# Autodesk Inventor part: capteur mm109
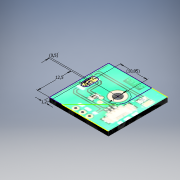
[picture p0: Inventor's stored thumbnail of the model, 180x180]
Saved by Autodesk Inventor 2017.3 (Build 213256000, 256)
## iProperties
Part Number: capteur mm109
Material: Générique
Document SubType Name: Modeling
Designer: ficho
Density: 1 g/cm^3
Appearance: Par défaut
Author: ficho
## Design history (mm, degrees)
sketch "Esquisse1"
  geometry: L1 (0, 0)-(22, 0); L2 (22, 0)-(22, 22); L3 (22, 22)-(0, 22); L4 (0, 22)-(0, 0); C1 r 1.5 at (9.5, 10); C2 r 0.5 at (20.359, 16); C3 r 0.5 at (20.359, 11); C4 r 0.5 at (20.359, 6)
  constraints: 8 end point, 4 centre point, 2 parallel, 1 horizontal, 1 perpendicular
  dimensions: "d0" = 22 distance of L3.end L2.end; "d1" = 22 distance of L2.end L1.end; "d2" = 3 diameter of C1; "d3" = 12.5 distance from line of L2 C1.centre; "d4" = 12 distance from line of C1.centre L3; "d5" = 6 distance from line of C2.centre L3 (computed from d6); "d6" = 5 distance of C3.centre C2.centre; "d7" = 5 distance of C4.centre C3.centre (= d6); "d8" = 1 diameter of C2; "d9" = 1 diameter of C3 (= d8); "d10" = 1 diameter of C4
extrude "Extrusion1" new body sketch "Esquisse1" distance "d11" = 1.6; taper "d12" = 0 deg
node "Plan de construction1"
sketch "Esquisse2"
  geometry: L1 (-75, 72.5)-(284.333, 72.5); L2 (284.333, 72.5)-(284.333, -43); L3 (284.333, -43)-(-75, -43); L4 (-75, -43)-(-75, 72.5); 1 further point; 1 other entity
  constraints: 2 other
  dimensions: "d17" = 115.5 distance between parallel lines of L3 L1; "d21" = 43 distance from line of L3 point (0, 0); "d22" = 75 distance from line of L4 point (0, 0)
feature "Décalcomanie1" sketch "Esquisse2"
sketch "Esquisse3"
  geometry: L1 (0, 0)-(-22, 0) reference; L2 (0, 22)-(0, 0) reference; L3 (-22, 22)-(0, 22) reference; L4 (-22, 0)-(-22, 22) reference; C1 r 1.5 at (-9.5, 10) reference; C2 r 0.5 at (-20.359, 6) reference; C3 r 0.5 at (-20.359, 11) reference; C4 r 0.5 at (-20.359, 16) reference; 1 further point
extrude "Extrusion2" join sketch "Esquisse3" stored distance "d25" = 1.6; taper "d26" = 0 deg
sketch "Esquisse4"
  geometry: L1 (0, 0)-(22, 0) reference; L2 (0, 22)-(0, 0) reference; C1 r 1.5 at (12.5, 13); C2 r 0.375 at (8.394, 1.4); C3 r 0.375 at (10.974, 1.4); C4 r 0.375 at (13.554, 1.4)
  constraints: 4 centre point
  dimensions: "d27" = 3 diameter of C1; "d28" = 0.75 diameter of C2; "d29" = 0.75 diameter of C3 (= d28); "d30" = 0.75 diameter of C4 (= d29); "d31" = 2.58 distance of C3.centre C2.centre; "d32" = 2.58 distance of C3.centre C4.centre (= d31); "d33" = 1.4 distance from line of C2.centre L1; "d34" = 1.4 distance from line of L1 C3.centre (= d33); "d35" = 1.4 distance from line of L1 C4.centre (= d33); "d36" = 12.5 distance from line of L2 C1.centre; "d37" = 13 distance from line of L1 C1.centre
extrude "Extrusion3" cut sketch "Esquisse4" stored distance "d38" = 1.6; taper "d39" = 0 deg
sketch "Esquisse5"
  geometry: L1 (2.45, 14)-(2.45, 11); L2 (1.2, 14)-(1.2, 11); L3 (3.7, 11)-(3.7, 14); L4 (0, 22)-(0, 0) reference; L5 (0, 22)-(0, 0); L6 (14.993, 10.543)-(4.604, 0); L7 (0, 0)-(22, 0) reference; L8 (4.604, 0)-(0, 0); L9 (16, 13)-(16, 22); L10 (22, 22)-(0, 22) reference; L11 (16, 22)-(0, 22); A1 r 1.25 centre (2.45, 14) between (3.7, 14) and (1.2, 14); A2 r 1.25 centre (2.45, 11) between (1.2, 11) and (3.7, 11); A3 r 3.5 centre (12.5, 13) between (14.993, 10.543) and (16, 13); 2 further points
  constraints: 18 end point, 6 point on circle, 6 tangent, 3 centre point, 3 collinear, 2 vertical, 1 coincident, 1 midpoint, 1 parallel, 1 point on line
  dimensions: "d43" = 3 distance of L1.start L1.end; "d44" = 2.5 diameter of A2; "d45" = 1.2 distance between parallel lines of L2 L4; "d46" = 12.5 vertical distance of L4.end point (2.45, 12.5); "d47" = 7 diameter of A3; "d48" = 0.5 vertical distance of point (2.45, 12.5) point (12.5, 13) (derived); "d49" = 10.05 horizontal distance of point (12.5, 13) point (2.45, 12.5) (derived)
node "Solide1"
node "Image1"
node "Boucle projetée1"
other parameters: "d13" = 1, "d23" = 15.22964, "d24" = 12.28514
